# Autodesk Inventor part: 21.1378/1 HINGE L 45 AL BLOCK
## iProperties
Created: 2007-01
Part Number: 21.1378/1 HINGE L 45 AL BLOCK
Document SubType Name: Modeling
Designer: Andy Moles
Material: Aluminum-6061
Mass: 18.3886 g
Surface Area: 42.4477 cm^2
Volume: 6.78548 cm^3
Density: 2.71 g/cm^3
Author: Andy Moles
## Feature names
1. Extrusion1
2. Hole1
